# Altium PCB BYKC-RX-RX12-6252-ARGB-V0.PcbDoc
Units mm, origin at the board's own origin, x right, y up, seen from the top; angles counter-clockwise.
Board outline 71.05 x 31.8 mm, 2 copper layers (Top Layer, Bottom Layer); 60 components, 98 nets, 230 pads, 255 vias.
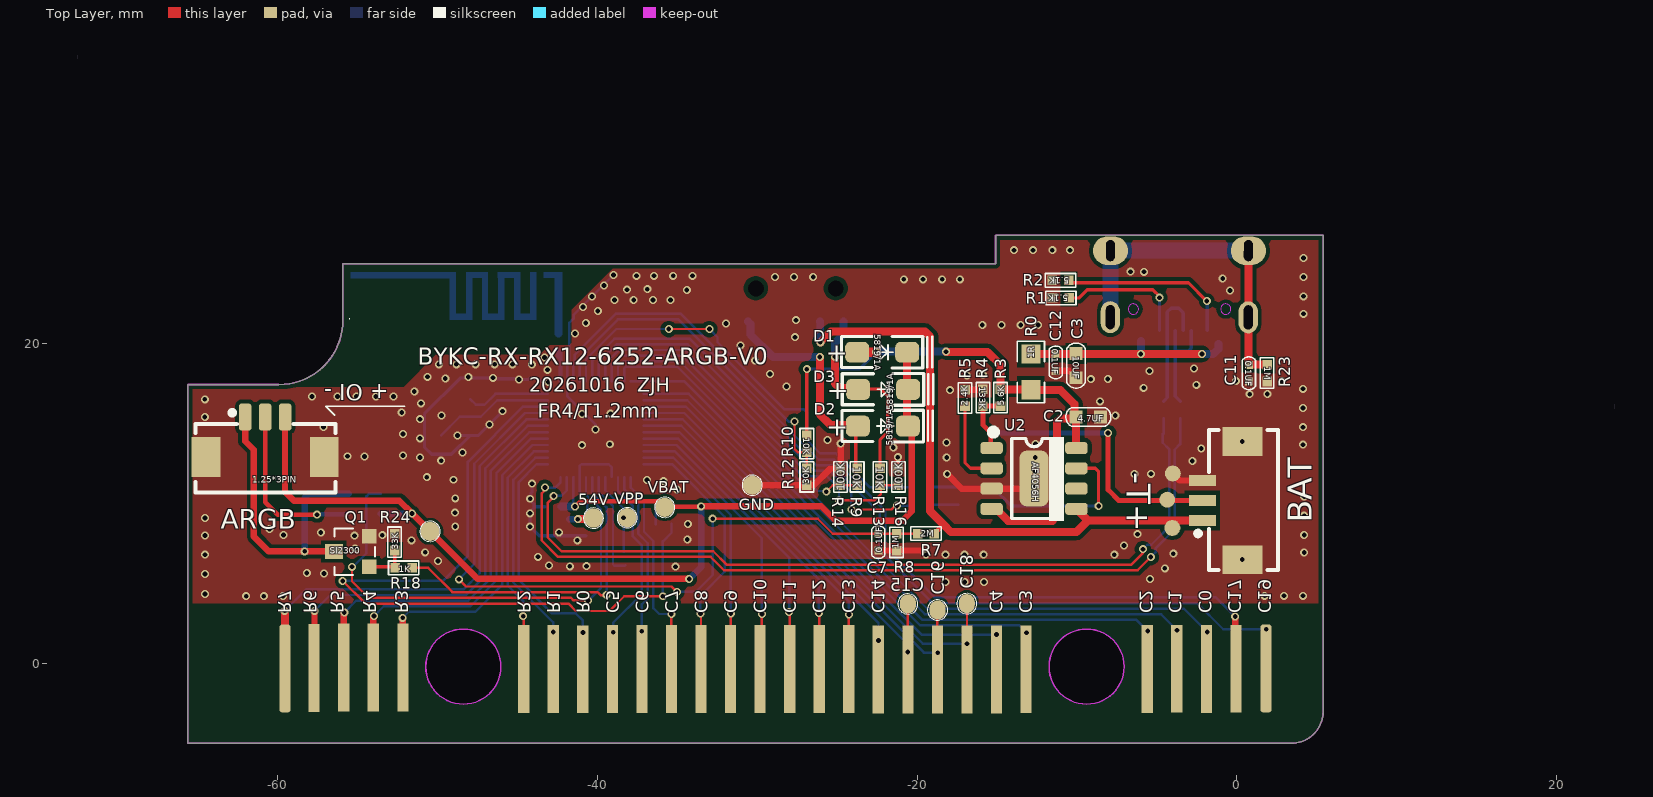
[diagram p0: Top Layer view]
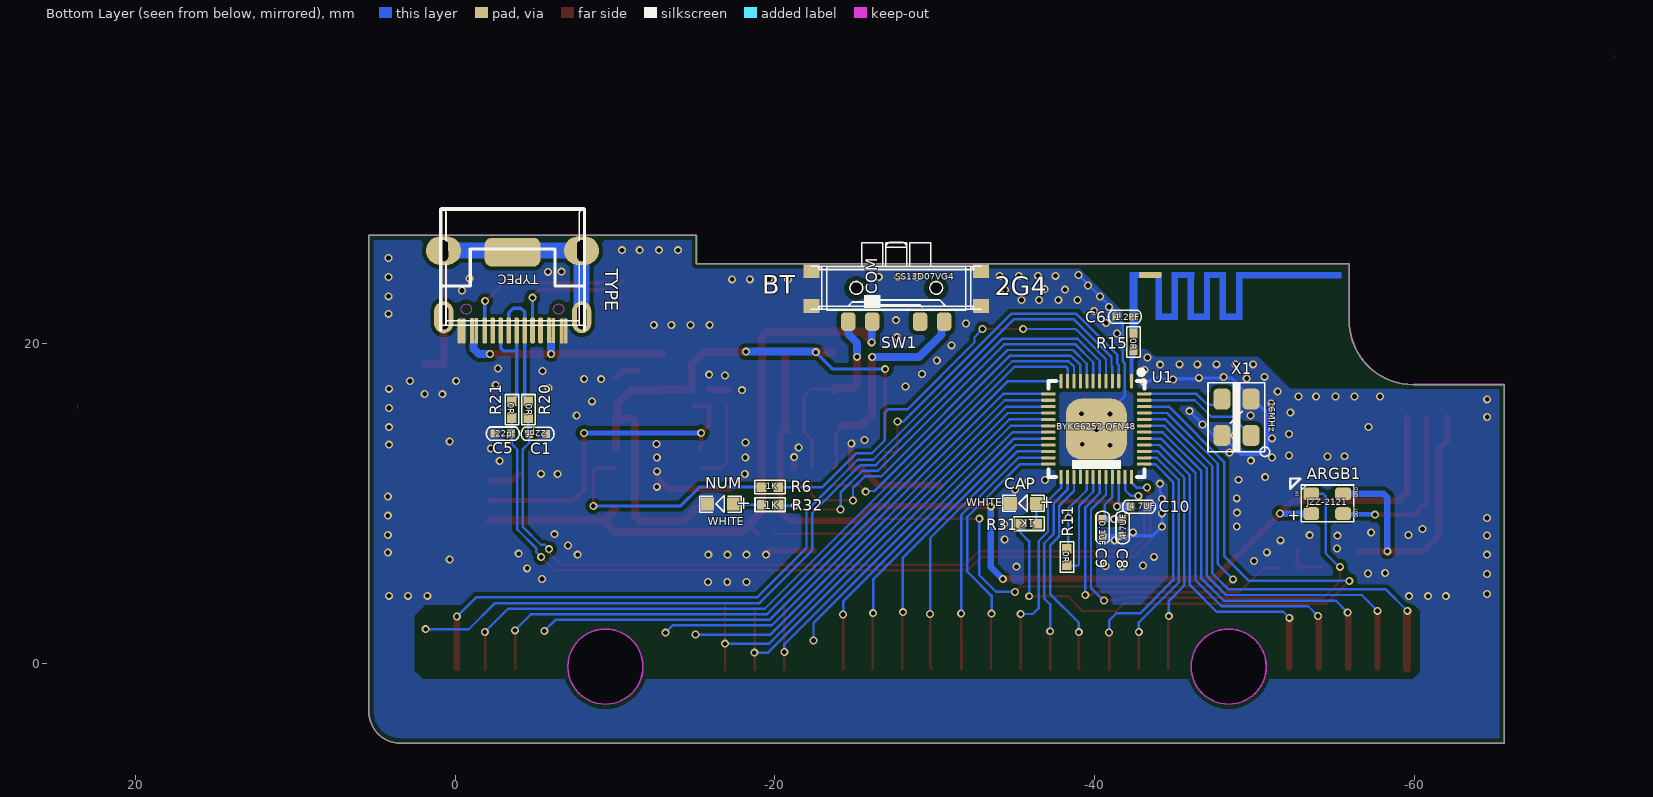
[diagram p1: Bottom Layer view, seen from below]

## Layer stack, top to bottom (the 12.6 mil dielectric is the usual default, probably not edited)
Top Solder: solder mask 0.0102, Solder Resist, Dk 3.5
Top Layer: signal copper 0.0356
Dielectric 1: dielectric 0.32, FR-4, Dk 4.8
Bottom Layer: signal copper 0.0356
Bottom Solder: solder mask 0.0102, Solder Resist, Dk 3.5

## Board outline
-65.644,-5.023 -65.644,17.427 -59.934,17.427 ccw(c-59.934,21.427) -55.934,21.427 -55.934,24.977 -15.094,24.977 -15.094,26.777 5.406,26.777 5.406,-3.023 cw(c3.406,-3.023) 3.406,-5.023
cut-out: -11.744,-0.223 ccw(c-9.394,-0.223) -9.394,-2.573 ccw(c-9.394,-0.223) -7.044,-0.223 ccw(c-9.394,-0.223) -9.394,2.127 ccw(c-9.394,-0.223)
cut-out: -50.744,-0.223 ccw(c-48.394,-0.223) -48.394,-2.573 ccw(c-48.394,-0.223) -46.044,-0.223 ccw(c-48.394,-0.223) -48.394,2.127 ccw(c-48.394,-0.223)

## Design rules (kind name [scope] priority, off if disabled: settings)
Clearance [All] p1: gap=0.199 ignorepadtopadclearanceinfootprint=FALSE except(0.25: Arc-Fill Arc-Poly Arc-Region Track-Fill Track-Poly Track-Region SMDPad-Fill SMDPad-Poly SMDPad-Region THPad-Fill THPad-Poly THPad-Region Via-Fill Via-Poly Via-Region Fill-Fill Fill-Poly Fill-Region Poly-Poly Poly-Region Region-Region)
DiffPairsRouting [All] p1: maxlimit=0.254 minlimit=0.2 mostfreqgap=0.2 toplayer_minwidth=0.2 toplayer_maxwidth=0.2 toplayer_prefwidth=0.2 bottomlayer_minwidth=0.2 bottomlayer_maxwidth=0.2 bottomlayer_prefwidth=0.2 maxuncoupledlength=12.7
PolygonConnect [All] p1: connectstyle=Direct reliefconductorwidth=0.254 reliefentries=4 polygonreliefangle="90 Angle" airgapwidth=0.254
RoutingVias [All] p1: holewidth=0.3 width=0.5 viastyle="Through Hole" minholewidth=0.3 minwidth=0.5 maxholewidth=0.3 maxwidth=0.5
SolderMaskExpansion [All] p1: expansion=0.102 istentingtop=FALSE
Width [All] p1: maxlimit=1 minlimit=0.15 preferedwidth=0.15
29 further rules are at their usual default settings.

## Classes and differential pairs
component class "BYKC_PX781MAX_6625(CD) V1.0": ARGB BAT C1 C2 C3 C5 C6 C8 C9 C10 D1 D2 D3 Q1 R1 R2 R3 R4 R5 R6 R7 R8 R10 R11 R12 R20 R21 SW1 U1 U2 X1

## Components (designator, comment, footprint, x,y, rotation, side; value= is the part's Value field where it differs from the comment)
54V "" TP_1.2C#1 -40.243,9.077 r270 top (schematic designator T3)
ARGB "1.25*3PIN" "3PIN 间距1.25MM"#1 -60.791,14.141 r0 top locked (schematic designator H2)
ARGB1 "JZZ-2121" ARGB-2121-JZZ -54.561,9.991 r90 bottom locked
BAT "" "3PIN 间距1.25MM"#2 -0.901,10.171 r90 top locked (schematic designator BAT1)
C1 "22pf" 0402c -5.152,14.344 r0 bottom value=30pF
C2 "4.7UF" 0603C -10.051,15.401 r0 top
C3 "10UF" 0603C -10.051,17.847 r90 top value=4.7UF
C5 "22pf" 0402c -2.975,14.359 r180 bottom value=30pF
C6 "1.2PF" 0402c -41.9,21.67 r180 bottom value=1.2pF
C7 "0.1UF" 0402c -22.431,7.566 r90 top value=30pF
C8 "4.7UF" 0402c -41.76,8.48 r270 bottom value=10uF
C9 "0.1uF" 0402c -40.51,8.48 r270 bottom
C10 "4.7UF" 0402c -42.781,9.781 r180 bottom value=10uF
C11 "0.1UF" 0402C 0.759,18.131 r270 top
C12 "0.1UF" 0402C -11.331,18.811 r90 top
CAP "WHITE" 0603LED -35.551,9.991 r0 bottom locked (schematic designator LED2)
D1 "5819/1A" 1206D#1 -22.14,19.45 r0 top
D2 "5819/1A" 1206D#2 -22.1,14.83 r0 top
D3 "5819/1A" 1206D#2 -22.08,17.12 r0 top
GND "" TP_1.2C#1 -30.325,11.14 r0 top (schematic designator T3)
NUM "WHITE" 0603LED -16.591,9.951 r0 bottom locked (schematic designator LED3)
Q1 "SI2300" SOT-23 -55.391,6.971 r90 top
R0 "1R" 0805R -12.881,18.221 r90 top value=5.1K (schematic designator R15)
R1 "5.1K" 0402R#1 -10.481,22.851 r180 top
R2 "5.1K" 0402R#1 -11.551,23.951 r0 top
R3 "5.6K" 0402R#1 -14.781,17.131 r270 top
R4 "133K" 0402R#1 -15.881,16.081 r90 top
R5 "2.4K" 0402R#1 -17.001,17.111 r270 top
R6 "1K" 0402R#1 -19.161,11.011 r180 bottom
R7 "2M" 0402R#1 -19.971,8.101 r0 top
R8 "1M" 0402R#1 -21.281,7.031 r90 top
R9 "10K" 0402R#1 -23.751,12.181 r270 top value=1K (schematic designator R10)
R10 "10K" 0402R#1 -26.901,14.251 r270 top
R11 "0R" 0402R#1 -38.27,6.11 r90 bottom
R12 "30K" 0402R#1 -26.901,11.131 r90 top
R13 "10K" 0402R#1 -22.321,12.181 r270 top value=1K (schematic designator R10)
R14 "100K" 0402R#1 -24.801,11.121 r90 top value=1K (schematic designator R10)
R15 "0R" 0402R#2 -42.431,19.571 r90 bottom (schematic designator R5)
R16 "100K" 0402R#1 -21.171,11.131 r90 top value=1K (schematic designator R10)
R18 "1K" 0402R#1 -51.601,5.961 r180 top (schematic designator R13)
R20 "0R" 0402R#1 -4.575,16.381 r270 bottom
R21 "0R" 0402R#1 -3.541,16.381 r270 bottom
R23 "1M" 0402R#3 1.899,18.141 r270 top
R24 "33K" 0402R#1 -52.691,7.041 r90 top value=1K (schematic designator R13)
R31 "1K" 0402R#1 -36.42,8.72 r0 bottom (schematic designator R10)
R32 "1K" 0402R#1 -19.181,9.911 r180 bottom (schematic designator R12)
SW1 "SS13D07VG4" "SW  贴片8PIN" -27.591,22.951 r180 bottom locked
T3 "" TP_1.2C#1 -50.471,8.231 r180 top
T3 "" TP_1.2C#2 -16.896,3.729 r0 top
T3 "" TP_1.2C#2 -18.726,3.329 r0 top
T3 "" TP_1.2C#2 -20.586,3.709 r0 top
TYPE "TYPEC" TYPE16-3D -3.601,23.991 r180 bottom locked
U1 "BYKC6252-QFN48" QFN48-6*6 -40.116,14.645 r180 bottom locked (schematic designator U4)
U2 "AF4056H" SOP8A -12.686,11.548 r0 top locked
VBAT "" TP_1.2C#1 -35.781,9.746 r270 top (schematic designator T3)
VPP "" TP_1.2C#1 -38.151,9.101 r0 top (schematic designator T3)
X1 "16MHz" 3D-3225-4P -48.881,15.381 r90 bottom
? "" ANT0 -46.451,23.381 r90 bottom locked
? "" P1#1 -59.531,-0.308 r180 top
? "" P1#2 -1.582,-0.305 r180 top

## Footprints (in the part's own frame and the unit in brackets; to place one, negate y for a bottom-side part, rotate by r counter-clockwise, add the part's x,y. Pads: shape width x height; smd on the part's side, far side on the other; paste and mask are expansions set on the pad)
3D-3225-4P [mm] "3.2*2.5*0.7mm(长宽高)"
  rrect50% 1.3x1.05 smd: 1(-1.14,-0.91) 2(-1.14,0.91) 3(1.14,0.91) 4(1.14,-0.91)
  silkscreen extent -2.46,-2.08 2.22,1.78, body extent -1.6,-1.25 1.6,1.25, height 0.7
"3PIN 间距1.25MM"#1 [mm]
  rrect50% 0.8x1.7 smd paste+0 mask+0.05: 1(-1.25,1.25) 2(0,1.25) 3(1.25,1.25)
  rect 1.8x2.5 smd paste+0 mask+0.05: 4(-3.7,-1.25) 5(3.7,-1.25)
  silkscreen extent -4.35,-3.47 4.4,1.67
"3PIN 间距1.25MM"#2 [mm]
  rect 0.7x1.7 smd paste+0 mask+0.05: 1(-1.25,1.25) 2(0,1.25) 3(1.25,1.25)
  rect 1.8x2.5 smd paste+0 mask+0.05: 4(-3.7,-1.25) 5(3.7,-1.25)
  silkscreen extent -4.35,-3.47 4.4,1.67
0402c [mm]
  rect 0.5x0.5 smd: 1(-0.525,0) 2(0.525,0)
  silkscreen extent -1.02,-0.42 1.02,0.41
0402C [mm]
  rect 0.5x0.5 smd: 1(-0.525,0) 2(0.525,0)
  silkscreen extent -1.02,-0.42 1.02,0.41, body extent -0.52,-0.28 0.54,0.28, height 0.25
0402R#1 [mm]
  rect 0.6x0.6 smd: 1(0,0) 2(1.05,0)
  silkscreen extent -0.42,-0.42 1.47,0.42
0402R#2 [mm]
  rect 0.6x0.5 smd: 1(0,0) 2(1.05,0)
  silkscreen extent -0.42,-0.43 1.47,0.42
0402R#3 [mm]
  rect 0.6x0.6 smd: 1(-0.525,0) 2(0.525,0)
  silkscreen extent -0.95,-0.42 0.95,0.42, body extent -0.59,-0.19 0.63,0.22, height 0.25
0603C [mm]
  rect 0.8x0.8 smd: 1(0,0) 2(1.524,0)
  silkscreen extent -0.65,-0.58 2.17,0.58
0603LED [mm]
  rect 0.8x0.8 smd: 1(-0.8,0) 2(0.8,0)
  silkscreen extent -1.3,-0.53 1.3,0.51, body extent -0.85,-0.45 0.85,0.45, height 0.9
0805R [mm]
  rect 1.2x1.2 smd: 1(-1.125,0) 2(1.125,0)
  silkscreen extent -1.92,-0.85 1.92,0.85
1206D#1 [mm]
  rrect50% 1.5x1.3 smd: 2(1.52,0) D(-1.61,0)
  silkscreen extent -2.6,-0.99 3.08,0.99, body extent -1.84,-0.8 1.86,0.8, height 1.2
1206D#2 [mm]
  rrect50% 1.5x1.3 smd: 1(-1.61,0) 2(1.52,0)
  silkscreen extent -2.6,-0.99 3.08,0.99, body extent -1.84,-0.8 1.86,0.8, height 1.2
ANT0 [mm]
  rrect50% 0.4x1.4 smd: 1(0.9,2.96)
  Top Layer region: -1.501,2.34 -1.501,1.489 -1.901,1.489 -1.901,2.34
  Top Layer region: 0.696,-2.4 1.095,-2.4 1.095,-9.017 0.696,-9.017
  Top Layer region: 1.097,1.633 1.097,1.233 -1.903,1.233 -1.903,1.633
  Top Layer region: 1.098,1.34 1.098,0.211 0.698,0.211 0.698,1.34
  Top Layer region: 0.85,0.633 0.85,0.211 -1.902,0.211 -1.902,0.633
  Top Layer region: -1.503,0.36 -1.503,-0.59 -1.903,-0.59 -1.903,0.36
  Top Layer region: 1.099,-0.389 1.099,-0.789 -1.903,-0.789 -1.903,-0.389
  Top Layer region: 1.098,-0.68 1.098,-1.783 0.701,-1.783 0.701,-0.68
  Top Layer region: 0.9,-1.384 0.9,-1.784 -1.904,-1.784 -1.904,-1.384
  Top Layer region: -1.505,-1.56 -1.505,-2.65 -1.905,-2.65 -1.905,-1.56
  Top Layer region: 1.096,-2.401 1.096,-2.801 -1.904,-2.801 -1.904,-2.401
  Top Layer region: 1.1,2.641 1.1,2.241 -1.902,2.241 -1.902,2.641
ARGB-2121-JZZ [mm] "JZZ晶之"
  rrect50% 0.8x1 smd: 1(-0.64,-1) 2(0.6,-1) 3(-0.64,1) 4(0.6,1)
  silkscreen extent -1.15,-1.65 1.56,2.32, body extent -1.4,-1.76 1.4,1.74, height 0.21
P1#1 [mm] "金手指"
  rect 0.7x5.5 smd: 1(-1.791,0.002)
P1#2 [mm] "金手指"
  rect 0.7x5.5 smd: 1(-1.531,0.054)
QFN48-6*6 [mm]
  rrect50% 0.19x0.9 smd paste-100 mask+0.051: 1(2.2,3) 3(1.4,3) 4(1,3) 5(0.6,3) 6(0.2,3) 7(-0.2,3) 8(-0.6,3) 9(-1,3) 10(-1.4,3) 11(-1.8,3) 12(-2.2,3) 25(-2.2,-3) 26(-1.8,-3) 27(-1.4,-3) 28(-1,-3) 29(-0.6,-3) 30(-0.2,-3) 31(0.2,-3) 32(0.6,-3) 33(1,-3) 34(1.4,-3) 35(1.8,-3) 36(2.2,-3)
  rrect50% 0.45x1.5 on Bottom Overlay paste-100 mask+0.051: 2(1.8,3)
  rrect50% 0.9x0.19 smd paste-100 mask+0.051: 13(-3,2.2) 14(-3,1.8) 15(-3,1.4) 16(-3,1) 17(-3,0.6) 18(-3,0.2) 19(-3,-0.2) 20(-3,-0.6) 21(-3,-1) 22(-3,-1.4) 23(-3,-1.8) 24(-3,-2.2) 37(3,-2.2) 38(3,-1.8) 39(3,-1.4) 40(3,-1) 41(3,-0.6) 42(3,-0.2) 43(3,0.2) 44(3,0.6) 45(3,1) 46(3,1.4) 47(3,1.8) 48(3,2.2)
  rrect50% 3.8x3.8 smd paste-100 mask+0.051: 49(0.001,-0.001)
  silkscreen extent -3,-3 3,3.7
SOP8A [mm] "5*6*1.8mm（长宽高）"
  rrect50% 1.4x0.75 smd: 1(-2.65,1.905) 2(-2.65,0.635) 3(-2.65,-0.635) 4(-2.65,-1.905) 5(2.65,-1.905) 6(2.65,-0.635) 7(2.65,0.635) 8(2.65,1.905)
  rrect50% 1.8x3.5 smd: 9(0,0)
  silkscreen extent -2.69,-2.66 1.89,3.05, body extent -3,-2.5 3,2.5, height 1.9
SOT-23 [mil]
  rect 36x36 smd: 1(-37.5,-43.48) 2(37.5,-43.48)
  rect 36x43.94 smd: 3(0.5,43.48)
  silkscreen extent -58,-57 57,42
"SW  贴片8PIN" [mm]
  rrect50% 0.9x1.15 smd: 1(-3,-1.588) 2(-1.5,-1.588) 3(1.5,-1.588) 4(3,-1.588)
  rect 1x0.9 smd: 5(-5.3,-0.613) 6(-5.3,1.587) 7(5.3,1.587) 8(5.3,-0.613)
  round 0 hole 1: ""(-2.5,0.5) ""(2.5,0.5)
  silkscreen extent -4.35,-0.86 4.35,3.34
TP_1.2C#1 [mm]
  round 1.2 smd: 1(0.006,-0.009)
  silkscreen extent -0.63,-0.64 0.64,0.63
TP_1.2C#2 [mm]
  oval 1x1.2 smd: 1(0.006,-0.009)
  silkscreen extent -0.63,-0.64 0.64,0.63
TYPE16-3D [mm]
  oval 2.2x1.8 hole 0.55 slot 1.3 at 90.55 deg: 0(-4.33,1.81) 0(4.3,1.81)
  oval 1.2x2 hole 0.55 slot 1.5 at 90.55 deg: 0(-4.32,-2.36) 0(4.31,-2.35)
  rrect50% 3.5x1.8 smd: 0(-0.01,1.72)
  rrect50% 0.23x1.55 smd: 1(-3.34,-3.22) 2(-3.08,-3.22) 15(3.06,-3.22) 16(3.32,-3.22)
  rrect50% 0.23x1.6 smd: 3(-2.55,-3.2) 4(-2.29,-3.2) 13(2.27,-3.18)
  rrect50% 0.3x1.6 smd: 5(-1.758,-3.183) 6(-1.258,-3.183) 7(-0.758,-3.183) 8(-0.258,-3.183) 9(0.242,-3.183) 10(0.742,-3.183) 11(1.242,-3.183) 12(1.742,-3.183)
  rrect50% 0.23x1.58 smd: 14(2.53,-3.19)
  Keep-Out Layer circle w0.05: c-2.913,-1.843 r0.325
  Keep-Out Layer circle w0.05: c2.867,-1.843 r0.325
  silkscreen extent -4.51,-3.14 4.49,4.41, body extent -4.49,-3.57 4.45,4.33, height 3.25

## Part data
54V GND T3 T3 T3 T3 VBAT VPP: library part TEST_POINT
ARGB: library part PZ254V-11-03P, Color=黑色, Current Rating (Max)=3A, JLCPCB Part Class="Extended Part", LCSC Part Name="间距:2.54mm 1x3P 直插 方针", Manufacturer=XFCN(兴飞), Operating Temperature Range=-40℃~+105℃, Voltage Rating (Max)=250V
BAT: library part Battery, "Multicell Battery"
C1 C5 C6 C7 C8 C9 C10: library part CAP_0603
C2 C3: library part Cap, "Capacitor"
CAP NUM: library part LED_0603-R
D1: library part "D Schottky", "Schottky Diode"
D2 D3: library part D_1N4007A
Q1: library part SI2301-ZE, Continuous Drain Current (Id)=2.3A, Drain Source On Resistance (RDS(on)@Vgs,Id)=126mΩ@4.5V, Drain Source Voltage (Vdss)=20V, Gate Threshold Voltage (Vgs(th)@Id)=1V@250uA, Input Capacitance (Ciss@Vds)=285pF, JLCPCB Part Class="Extended Part", LCSC Part Name="1个P沟道 耐压:20V 电流:2.3A", Manufacturer="HXY MOSFET(华轩阳电子)", Manufacturer Part=SI2300-ZE, Power Dissipation (Pd)=700mW
R0 R1 R2 R7 R8 R9 R10 R11 R12 R13 R14 R16 R18 R20 R21 R24 R31 R32: library part Res_0603
R3 R4 R5 R6 R15: library part Res2, "Resistor"
SW1: Actuator Color=-, Current Rating (DC)=500mA, JLCPCB Part Class="Extended Part", LCSC Part Name="4脚3三档位SS13D07VG2 1P3T立式拨动开关,柄长4MM", Manufacturer="SHOU HAN(首韩)", Operating Temperature=-10℃~+50℃, Voltage Rating (DC)=50V
U1: library part "BYC6625 QFN48"
U2: library part "4057 SOP-8"
X1: library part XL7EL89COI-111YLC-16M, Equivalent Series Resistance (ESR)=-, External load capacitor=12pF, Frequency Stability(Full temperature range)=±20ppm, JLCPCB Part Class="Extended Part", LCSC Part Name="16MHz ±10ppm 12pF", Manufacturer=YXC(扬兴晶振), Normal temperature Frequency Tolerance=±10ppm, Operating Temperature=-40℃~+85℃

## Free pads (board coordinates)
  rect 0.7x5.5 smd: 1(-1.891,-0.379) 4(-3.751,-0.359) 5(-5.597,-0.378) 6(-13.181,-0.389) 7(-15.03,-0.403) 8(-16.879,-0.409) 9(-18.728,-0.409) 10(-20.577,-0.396) 11(-22.426,-0.396) 12(-24.275,-0.384) 13(-26.124,-0.377) 14(-27.974,-0.371) 15(-29.823,-0.371) 16(-31.672,-0.371) 17(-33.521,-0.365) 18(-35.37,-0.36) 19(-37.219,-0.384) 20(-39.068,-0.377) 21(-40.917,-0.39) 22(-42.766,-0.36) 23(-44.615,-0.372) 25(-54.031,-0.279) 26(-55.881,-0.279) ""(-52.171,-0.275)
  round 1 smd: 27(-4.001,11.861) 28(-4.351,10.221) 29(-4.031,8.451)
  rrect50% 0.7x5.5 smd: 30(-59.56,-0.34) 30(1.83,-0.34)

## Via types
v1: diameter 0.5, hole 0.3, Top Layer to Bottom Layer, 255 vias

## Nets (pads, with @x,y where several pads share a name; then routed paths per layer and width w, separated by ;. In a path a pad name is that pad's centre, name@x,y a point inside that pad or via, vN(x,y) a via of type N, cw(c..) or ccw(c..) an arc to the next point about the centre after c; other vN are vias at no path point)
001: ARGB1.1 ARGB.2 | length 10.9
  Top Layer w0.3: ARGB.2 -60.791,10.061 -60.011,9.281 v1(-57.551,9.281)
  Bottom Layer w0.3: v1(-57.551,9.281) -57.516,9.316 -55.596,9.316 ARGB1.1
002: 
2G4: R9.2 R14.1 U1.9 | length 20.4
  Top Layer w0.15: v1(-25.681,10.721) -25.281,11.121 R14.1 ; R14.1@-24.791,11.131 R9.2 R9.2@-23.681,11.131
  Bottom Layer w0.15: U1.9 -39.116,18.639 -38.517,19.238 -34.709,19.238 -26.24,10.768 -25.729,10.768 v1(-25.681,10.721)
003: 
004: 
005: 
5V: C2.1 D1.D R0.1 R3.1 R10.1 U2.4 U2.8 | length 38.9
  Top Layer w0.2: R10.1@-26.901,14.451 -26.901,18.389 v1(-26.9,18.39)
  Top Layer w0.5: v1(-18.19,19.48) -18.181,19.471 -15.591,19.471 -14.781,18.661 R3.1 ; U2.4 -15.011,9.643 -14.886,9.518 -14.886,9.476 -14.31,8.9 -11.544,8.9 -11.251,9.193 -11.251,15.111 -11.071,15.291 C2.1@-10.051,15.291 ; R3.1@-14.701,17.131 -12.981,17.131 -12.941,17.091 -11.041,17.091 -10.147,16.197 -10.147,15.386 C2.1@-10.051,15.291 ; U2.8 -10.051,13.469 C2.1@-10.051,15.291
  Top Layer w0.6: D1.D@-23.6,19.45 v1(-22.56,19.45)
  Bottom Layer w0.2: v1(-26.9,18.39) -23.62,18.39 v1(-22.56,19.45)
  Bottom Layer w0.5: v1(-22.56,19.45) -22.53,19.48 v1(-18.19,19.48)
5VLVD: C7.2 R7.1 R8.2 U1.45 | length 46.9
  Top Layer w0.15: v1(-48.67,5.24) -48.219,4.789 -35.369,4.789 v1(-35.03,4.45) ; v1(-32.79,9.03) -26.22,9.03 -25.281,8.091 C7.2 -19.981,8.091 R7.1
  Bottom Layer w0.15: v1(-48.67,5.24) -47.713,6.197 -47.713,12.475 -44.544,15.645 U1.45 ; v1(-35.03,4.45) -33.85,4.45 -32.79,5.51 v1(-32.79,9.03)
006: 
007: 
008: 
009: 
54E_CTRL: R18.1 U1.31 | length 20.6
  Top Layer w0.15: R18.1 -50.601,5.961 -49.08,4.44 -39.993,4.44 -39.804,4.251 v1(-39.421,4.251)
  Bottom Layer w0.15: U1.31 -40.316,10.629 -39.43,9.743 v1@-39.43,4.251
BAT+: BAT.1 pad.29 R7.2 SW1.2 U2.5 | length 39.2
  Top Layer w0.3: R7.2 -18.356,8.666
  Top Layer w0.5: v1(-26.06,20.07) -25.38,20.75 -19.5,20.75 -19.19,20.44 -19.19,9.5 -19.17,9.48 -18.356,8.666 -17.891,8.201 -10.034,8.201 -9.314,8.921 ; U2.5 -9.314,8.921 ; BAT.1 -9.314,8.921
  Bottom Layer w0.5: SW1.2 -26.061,21.333 -26.061,20.071 v1(-26.06,20.07)
BT: R13.2 R16.1 U1.8 | length 24.9
  Top Layer w0.15: v1(-24.89,10.18) -22.652,10.18 -22.261,10.571 -22.261,10.971 -22.261,11.071 R13.2 -22.261,11.131 R16.1
  Bottom Layer w0.15: U1.8 -39.516,18.733 -38.662,19.587 -34.565,19.587 -26.657,11.679 -25.619,11.679 -24.89,10.95 v1(-24.89,10.18)
C0: pad.1 U1.10 | length 47.3
  Top Layer w0.15: pad.1 -1.89,-0.378 pad.1@-1.89,1.95
  Bottom Layer w0.15: U1.10 -38.716,18.546 -38.373,18.889 -34.854,18.889 -19.366,3.401 -3.301,3.401 v1(-1.85,1.95)
C1: pad.4 U1.11 | length 44.7
  Top Layer w0.15: pad.4 pad.4@-3.751,2.05
  Bottom Layer w0.15: U1.11 -38.316,18.452 -38.228,18.54 -34.998,18.54 -19.51,3.052 -4.732,3.052 v1(-3.73,2.05)
C1A: 
C2: pad.5 U1.12 | length 38.8
  Bottom Layer w0.15: U1.12 -34.597,17.645 -19.655,2.703 -6.273,2.703 v1(-5.57,2)
C2A: 
C3: pad.6 U1.13 | length 30.2
  Bottom Layer w0.15: U1.13 -34.29,16.845 -19.8,2.354 -13.604,2.354 v1(-13.15,1.9)
C4: pad.7 U1.14 | length 28.2
  Bottom Layer w0.15: U1.14 -34.384,16.445 -19.719,1.78 v1(-15.04,1.78)
C5: pad.20 U1.27 | length 13.4
  Top Layer w0.15: pad.20 -39,-0.31 pad.20@-39,1.93
  Bottom Layer w0.15: v1(-39.02,1.93) -39.02,2.52 -37.221,4.319 -37.221,7.361 -37.801,7.941 -37.801,9.851 -38.716,10.766 U1.27
C6: pad.19 U1.26 | length 12.8
  Top Layer w0.15: pad.19 pad.19@-37.219,1.99
  Bottom Layer w0.15: U1.26 -38.316,10.859 -37.441,9.985 -37.441,8.075 -36.859,7.493 -36.859,4.041 -37.23,3.67 v1(-37.23,1.99)
C7: pad.18 U1.25 | length 13.5
  Top Layer w0.15: v1(-35.38,3.07) -35.38,-0.349 pad.18
  Bottom Layer w0.15: U1.25 -37.916,10.976 -37.092,10.152 -37.092,8.22 -36.51,7.637 -36.51,3.44 -36.14,3.07 v1(-35.38,3.07)
C8: pad.17 U1.24 | length 16.6
  Top Layer w0.15: v1(-33.56,3.09) -33.521,3.051 pad.17
  Bottom Layer w0.15: U1.24 -35.335,12.445 -32.04,9.15 -32.04,5.72 -33.56,4.2 v1(-33.56,3.09)
C9: pad.16 U1.23 | length 18.6
  Top Layer w0.15: pad.16 -31.66,-0.36 v1(-31.66,3.11)
  Top Layer w0.18: pad.16 pad.16@-31.672,1.631
  Bottom Layer w0.15: U1.23 -35.242,12.845 -31.66,9.263 v1(-31.66,3.11)
C10: pad.15 U1.22 | length 17.9
  Top Layer w0.15: pad.15 -29.71,-0.259 v1(-29.71,3.07)
  Bottom Layer w0.15: U1.22 -35.148,13.245 -29.71,7.807 v1(-29.71,3.07)
C11: pad.14 U1.21 | length 19
  Top Layer w0.15: v1(-28.01,3.18) -27.974,3.144 pad.14
  Bottom Layer w0.15: U1.21 -35.055,13.645 -28.01,6.6 v1(-28.01,3.18)
C12: pad.13 U1.20 | length 20.2
  Top Layer w0.15: v1(-26.15,3.12) -26.124,3.094 pad.13
  Bottom Layer w0.15: U1.20 -34.961,14.045 -26.15,5.234 v1(-26.15,3.12)
C13: pad.12 U1.19 | length 21.5
  Top Layer w0.15: pad.12 -24.27,-0.378 v1(-24.27,3.04)
  Bottom Layer w0.15: U1.19 -34.868,14.445 -24.27,3.847 v1(-24.27,3.04)
C14: pad.11 U1.18 | length 20.9
  Bottom Layer w0.15: U1.18 -34.758,14.845 -22.415,2.502 -22.415,1.415 v1(-22.42,1.41)
C15: pad.10 T3.1@-20.58,3.7 U1.17 | length 26.9
  Top Layer w0.15: T3.1@-20.58,3.7 -20.577,3.697 pad.10
  Bottom Layer w0.15: U1.17 -34.665,15.245 -20.595,1.175 -20.595,0.705 v1(-20.59,0.7)
C16: pad.9 T3.1@-18.72,3.32 U1.16 | length 28.3
  Top Layer w0.15: pad.9 -18.728,3.312 T3.1@-18.72,3.32
  Bottom Layer w0.15: U1.16 -34.571,15.645 -19.576,0.65 v1(-18.71,0.65)
C17: ?.1@-0.051,-0.359 U1.4 | length 55.8
  Top Layer w0.15: ?.1@-0.1,-0.31 ?.1@-0.051,-0.359
  Top Layer w0.4: ?.1@-0.1,-0.31 v1(-0.1,2.91)
  Bottom Layer w0.15: U1.4 -41.116,18.55 -41.065,18.601 -41.065,19.158 -38.723,21.5 -34.934,21.5 -26.16,12.726 -25.185,12.726 -21.981,9.522 -21.981,7.191 -18.92,4.13 -1.32,4.13 v1(-0.1,2.91)
C18: pad.8 T3.1@-16.89,3.72 U1.15 | length 30.5
  Top Layer w0.15: T3.1@-16.89,3.72 -16.879,3.709 pad.8
  Bottom Layer w0.15: U1.15 -34.478,16.045 -19.647,1.214 -16.884,1.214 v1(-16.88,1.21)
C18A: 
C19: pad.30@1.83,-0.34 U1.6 | length 52.9
  Bottom Layer w0.15: U1.6 -40.316,18.92 -38.951,20.285 -34.212,20.285 -26.304,12.377 -25.33,12.377 -22.33,9.377 -22.33,7.046 -19.034,3.75 -2.48,3.75 -0.845,2.115 1.845,2.115 v1(1.85,2.12)
CAP: R31.2 U1.46 | length 46.7
  Top Layer w0.15: v1(-55.94,5.14) -54.52,3.72 -41.82,3.72 -41.36,3.26 -39.25,3.26 -38.33,4.18 v1(-35.91,4.18)
  Bottom Layer w0.15: v1(-55.94,5.14) -49.67,5.14 -48.11,6.7 -48.11,12.59 -44.655,16.045 U1.46 ; v1(-35.91,4.18) -35.91,7.61 -35.37,8.15 R31.2
CD: R6.2 U1.5 | length 28
  Top Layer w0.15: v1(-35.54,20.9) v1(-33,20.9)
  Bottom Layer w0.15: U1.5 -40.716,19.013 -38.83,20.9 v1(-35.54,20.9) ; v1(-33,20.9) -32.49,20.39 -32.49,20.07 -28.29,15.87 -27.08,15.87 -26.88,15.67 -26.88,13.94 -26.06,13.12 -25.086,13.12 -22.977,11.011 R6.2
CHECK_5V: R10.2 R12.2 U1.3 | length 22.9
  Top Layer w0.15: v1@-27.671,15.11 -27.671,13.391 -27.481,13.201 R10.2 R12.2
  Bottom Layer w0.15: U1.3 -41.516,18.644 -41.414,18.746 -41.414,19.303 -38.868,21.849 -34.779,21.849 -28.04,15.11 v1(-27.68,15.11)
D+: R21.1 TYPE.7 TYPE.9 | length 6.7
  Bottom Layer w0.2: TYPE.9 -3.843,19.531 ; R21.1 -3.843,16.683 -3.843,19.531 ; TYPE.7 -2.843,19.709 -3.021,19.531 -3.843,19.531
D-: R20.1 TYPE.8 TYPE.10 | length 8
  Bottom Layer w0.2: R20.1 -4.343,16.613 TYPE.10 -4.343,21.969 -4.111,22.201 -3.631,22.201 -3.343,21.913 TYPE.8
DM: C1.2 R20.2 U1.35 | length 52.2
  Top Layer w0.15: v1(-42.741,10.455) -42.741,10.386 -43.121,10.006 -43.121,7.871 -42.241,6.991 -32.761,6.991 -31.93,6.16 -6.592,6.16 -5.875,6.877 v1(-5.875,7.125)
  Bottom Layer w0.15: v1(-42.741,10.455) -42.716,10.481 -42.251,10.481 -41.916,10.816 U1.35 ; v1(-5.875,7.125) -5.6,7.4 -5.353,7.4 -4.23,8.522 -4.23,13.39 -4.627,13.787 C1.2 ; C1.2@-4.575,14.344 R20.2
DP: C5.2 R21.2 U1.36 | length 53.5
  Top Layer w0.15: v1(-43.29,10.98) -43.357,10.913 -43.357,10.752 -43.491,10.618 -43.491,7.671 -42.462,6.642 -32.912,6.642 -32.081,5.811 -6.2,5.811 v1(-5.381,6.63)
  Bottom Layer w0.15: v1(-43.29,10.98) -42.627,10.979 -42.316,11.29 U1.36 ; v1(-5.381,6.63) -5.076,6.935 -5.076,7.176 -3.881,8.371 -3.881,13.361 -3.541,13.701 R21.2
GND: ARGB.4 ARGB.5 BAT.3 BAT.4 BAT.5 C1.1 C2.2 C3.1 C5.1 C6.1 C7.1 C8.2 C9.2 C10.2 C11.2 C12.1 CAP.2 GND.1 NUM.2 pad.27 Q1.2 R1.2 R2.1 R4.2 R5.1 R8.1 R12.1 R14.2 R16.2 R23.2 R24.2 SW1.5 SW1.6 SW1.7 SW1.8 TYPE.1 TYPE.2 TYPE.15 TYPE.16 U1.49 U2.3 U2.9 X1.2 X1.4 | length 59.2
  Top Layer w0.4: GND.1@-30.38,11.07 GND.1 R12.1 -26.461,11.131 -25.421,12.171 -24.761,12.171 -24.786,12.195 -24.786,13.724 v1(-24.78,13.73) ; C7.1 -19.729,7.041 -19.471,6.783 v1(-19.443,6.783) ; v1(-21.211,12.881) -21.211,12.221 R16.2 ; v1(-18.12,11.83) -17.203,10.913 -13.321,10.913 U2.9 ; R5.1@-17.151,17.111 -15.901,17.111 R4.2 ; C12.1@-11.361,18.286 -10.49,18.286 C3.1 ; pad.27 -3.561,11.421 BAT.3
  Bottom Layer w0.15: U1.49@-40.117,14.917 -40.876,15.676 -41.885,16.685 -41.885,18.768 -41.763,18.89 -41.763,21.282 -41.494,21.551 -41.494,21.789 -40.951,22.331 v1(-40.341,22.941) -39.621,23.661 v1(-39.001,24.281)
  Bottom Layer w0.2: v1(-48.761,14.241) X1.2 ; v1(-45.941,15.761) -47.461,14.241 X1.2 ; v1(-44.101,11.221) -44.104,11.218 -44.104,10.671 -44.154,10.621 -44.154,10.338 v1(-44.211,10.281) -44.211,10.2 -43.981,9.97 -43.981,9.711 ; C10.2@-43.276,9.781 -43.911,9.781 -43.981,9.711 ; v1(-43.08,17.59) -43.137,17.647 -43.546,17.647 -43.73,17.831 -44.239,17.831 -44.33,17.74 v1(-44.92,17.74) -44.975,17.795 -46.496,17.795 -46.531,17.831 -48.081,17.831 -48.591,17.831 -50.831,15.591 -50.831,13.521 -50.371,13.061 -49.151,13.061 X1.2 ; C9.2@-40.711,7.966 -43.656,7.966 v1(-44.221,8.531) -44.221,9.452 -43.981,9.692 -43.981,9.711 ; U1.49 U1.49@-40.117,14.917
  other v1: -61.981,4.181 -60.881,4.181 -59.681,4.181 1.749,4.211 2.949,4.211 4.149,4.211 -64.561,4.321 -18.22,5.08 -17.02,5.08 -15.82,5.08 -5.421,5.261 -64.561,5.581 -57.11,5.6 -58.19,5.63 -4.501,5.931 -35.12,6.03 -41.731,6.051 -40.681,6.061 -43.031,6.101 -49.98,6.38 0.348,6.471 -43.721,6.651 -64.561,6.781 -18.231,6.783 -17.031,6.783 -15.831,6.783 -7.661,6.783 -3.971,6.841 -50.78,6.93 4.219,6.921 -55.171,7.171 -7.051,7.351 -51.631,7.681 -41.261,7.681 -34.38,7.74 -55.201,7.971 -64.561,7.981 -53.461,8.001 -59.65,8.02 4.219,8.021 -6.211,8.061 -57.311,8.171 -42.411,8.181 -60.53,8.39 -48.9,8.54 -34.35,8.71 -64.561,9.081 4.219,9.221 -44.221,9.371 -48.91,9.41 -48.9,10.31 4.219,10.421 -35.021,10.851 -12.61,11.03 -35.871,11.381 -36.901,11.451 -49.01,11.47 -50.68,11.63 -6.411,11.831 -5.361,11.841 -12.62,12 -2.781,12.641 -49.781,12.661 -51.101,12.861 -18.15,12.87 -12.61,12.87 -54.58,12.92 -55.65,12.94 -52.16,12.98 -48.451,13.181 -2.221,13.421 -21.491,13.481 -40.971,13.631 4.149,13.661 -39.231,13.691 -12.6,13.7 -18.16,13.8 0.348,13.871 -25.61,13.95 -51.101,14.061 -52.17,14.33 -40.121,14.611 -57.141,14.771 4.149,14.761 -46.761,14.931 -51.101,15.261 -64.571,15.401 -49.761,15.491 -7.601,15.491 -40.971,15.581 -39.191,15.601 -52.25,15.68 4.149,15.961 -51.051,16.251 -8.551,16.381 -64.571,16.501 -57.861,16.671 -56.271,16.671 -55.071,16.671 -53.871,16.671 -52.771,16.671 0.809,16.821 1.909,16.841 -51.461,16.991 -17.941,17.071 4.149,17.161 -5.821,17.221 -28.18,17.31 -2.531,17.411 -0.061,17.651 2.839,17.641 -9.131,17.761 -8.071,17.771 -49.521,17.811 -46.531,17.851 -48.081,17.901 -50.641,17.911 -16.88,18 -15.891,18.041 -29.2,18.09 -5.461,18.271 -43.121,18.351 -2.681,18.431 -49.931,18.691 -48.831,18.691 -47.631,18.691 -46.431,18.691 -45.321,18.691 -44.111,18.671 -30.13,18.93 -43.31,19.12 -31.05,19.88 -27.641,20.391 -41.41,20.62 -15.921,21.151 -14.721,21.151 -13.521,21.151 -12.421,21.151 -31.96,21.25 -40.73,21.27 -27.571,21.451 4.179,21.851 -39.98,22.02 -40.901,22.281 -38.931,22.711 -37.731,22.711 -36.531,22.711 -35.431,22.711 4.179,22.951 -0.431,23.311 -38.15,23.36 -34.41,23.35 -36.88,23.39 -39.591,23.631 -20.831,24.011 -19.631,24.011 -18.431,24.011 -17.331,24.011 -0.881,24.061 4.179,24.151 -28.901,24.161 -27.701,24.161 -26.501,24.161 -37.561,24.231 -36.461,24.231 -35.261,24.231 -34.061,24.231 -5.811,24.481 -6.651,24.491 4.179,25.351 -13.941,25.831 -12.741,25.831 -11.541,25.831 -10.441,25.831
LED_0: 
LED_1: 
LED_2: 
LED_3: 
LED_4: 
LED_5: 
LED_VDD: 
MODE_IO: 
NetANT1_1: ?.1@-43.491,24.281 C6.2 R15.1 R15.2 U1.1 | length 6
  Bottom Layer w0.25: R15.1 -42.316,19.456 U1.1
  Bottom Layer w0.3: -42.431,19.166 R15.1
  Bottom Layer w0.5: R15.2 -42.431,24.201
NetC7_2: 
NetC8_1: 
NetCON1_26: 
NetCON1_27: 
NetCON1_28: 
NetD2_1: D2.1 R9.1 SW1.4 | length 14.5
  Top Layer w0.2: D2.1@-24.311,14.881 -23.84,14.41 -23.84,12.34 R9.1@-23.681,12.181
  Top Layer w0.5: v1(-26.09,19.15) -26.09,15.56 -25.419,14.888 -24.219,14.888 D2.1@-24.211,14.881
  Bottom Layer w0.5: SW1.4 -30.436,21.208 -30.436,20.566 -29.02,19.15 v1(-26.09,19.15)
NetD3_1: D3.1 R13.1 SW1.1 | length 12.5
  Top Layer w0.2: D3.1@-23.69,17.151 -22.287,17.151 -21.84,16.704 -21.84,14.441 -22.321,13.96 R13.1
  Top Layer w0.5: v1(-25.14,19.16) -25.14,17.496 -24.847,17.203 -23.803,17.203 D3.1@-23.69,17.09
  Bottom Layer w0.5: v1(-25.14,19.16) -25.14,20.04 -24.591,20.589 SW1.1
NetH2_1: ARGB1.2 ARGB.1 Q1.3 | length 19.3
  Top Layer w0.4: ARGB.1 -62.041,13.881 -61.5,13.34 -61.5,7.92 -60.564,6.984 Q1.3
  Bottom Layer w0.4: v1(-58.321,6.991) -58.321,10.357 -58.087,10.591 ARGB1.2
NetLED1_2: 
NetLED2_2: CAP.1 R31.1 | length 1.3
  Bottom Layer w0.15: R31.1@-36.361,8.69 -36.351,8.7 CAP.1
NetLED3_2: NUM.1 R32.1 | length 1.7
  Bottom Layer w0.15: R32.1 NUM.1@-17.431,9.911
NetQ1_1: Q1.1 R18.2 R24.1 | length 2.7
  Top Layer w0.2: Q1.1@-54.181,6.021 R18.2@-52.711,6.021 ; R24.1@-52.691,7.111 -52.691,6.041 R18.2@-52.711,6.021 ; R18.2 R18.2@-52.711,6.021
NetQ2_1: 
NetR1_1: R1.1 TYPE.11 | length 8.2
  Top Layer w0.2: R1.1 -9.861,22.851 -9.351,23.361 -5.251,23.361 -4.831,22.942 v1(-4.831,22.861)
  Bottom Layer w0.2: TYPE.11 -4.837,20.814 -4.837,22.855 v1(-4.831,22.861)
NetR2_2: R2.2 TYPE.5 | length 11
  Top Layer w0.2: R2.2 -10.351,23.801 -3.021,23.801 v1(-1.871,22.651)
  Bottom Layer w0.2: TYPE.5 TYPE.5 v1@-1.841,22.651
NetR5_2: R5.2 U2.2 | length 5.3
  Top Layer w0.2: R5.2 -17.001,12.523 -16.661,12.183 U2.2
NetR6_1: R6.1 U2.7 | length 14.6
  Top Layer w0.2: U2.7 -8.849,12.183 -8.641,11.976 v1(-8.641,9.821)
  Bottom Layer w0.2: R6.1 -15.281,11.011 -14.091,9.821 v1(-8.641,9.821)
NetR11_1: R11.1 U1.30 | length 6.6
  Bottom Layer w0.15: U1.30 -39.916,10.722 -39.031,9.837 -39.031,6.179 -38.944,6.091 -38.289,6.091 R11.1
NetU1_12: 
NetU4_47: U1.47 X1.1 | length 7.6
  Bottom Layer w0.15: X1.1 -48.621,15.411 -47.301,15.411 -46.268,16.445 U1.47
NetU4_48: U1.48 X1.3 | length 5.3
  Bottom Layer w0.15: X1.3 -47.611,16.161 -47.069,16.161 -46.385,16.845 U1.48
NTC: BAT.2 pad.28 R3.2 R4.1 U2.1 | length 20.9
  Top Layer w0.3: U2.1 -15.391,13.508 -15.391,14.411 -15.881,14.901 R4.1 R3.2@-14.921,16.081 ; v1(-8.051,14.391) -8.051,10.831 -7.391,10.171 BAT.2
  Bottom Layer w0.3: v1(-15.391,14.401) -15.386,14.396 -8.056,14.396 v1(-8.051,14.391)
NUM: R32.2 U1.7 | length 26.3
  Top Layer w0.15: v1(-24.11,9.61) -21.595,9.61 -21.355,9.85 v1(-21.26,9.85)
  Bottom Layer w0.15: U1.7 -39.916,18.826 -38.807,19.936 -34.357,19.936 -26.449,12.028 -25.474,12.028 -24.11,10.664 v1(-24.11,9.61) ; v1(-21.26,9.85) -20.292,9.85 R32.2
PWM: ARGB1.4 U1.32 | length 30.4
  Top Layer w0.15: v1(-55.36,6.02) -55.36,5.12 -54.33,4.09 -41.66,4.09 -41.491,3.921 -40.598,3.921 v1(-40.591,3.914)
  Bottom Layer w0.15: v1(-55.36,6.02) -55.31,6.02 -54.461,6.869 -54.461,10.431 -54.301,10.591 ARGB1.4 ; U1.32 -40.716,10.535 -39.779,9.598 -39.779,4.691 -40.556,3.914 v1(-40.591,3.914)
PWM_OFF: 
R0: pad.21 U1.37 | length 16.5
  Top Layer w0.15: pad.21 -40.91,-0.383 v1(-40.91,1.92)
  Bottom Layer w0.15: U1.37 -43.796,12.445 -44.921,11.319 -44.921,5.191 -42.84,3.11 -41.36,3.11 -40.91,2.66 v1(-40.91,1.92)
R1: pad.22 U1.38 | length 15.6
  Top Layer w0.15: pad.22@-42.78,1.94 -42.78,-0.346 pad.22
  Bottom Layer w0.15: U1.38 -43.889,12.845 -45.27,11.464 -45.27,5.047 -42.77,2.546 v1(-42.77,1.94)
R2: pad.23 U1.39 | length 15.6
  Top Layer w0.15: v1(-44.65,2.93) -44.615,2.895 pad.23
  Bottom Layer w0.15: v1(-44.65,2.93) -44.65,3.89 -45.619,4.859 -45.619,11.608 -43.983,13.245 U1.39
R3: pad. U1.40 | length 20.7
  Top Layer w0.15: pad.@-52.19,-0.256 pad.
  Top Layer w0.4: pad.@-52.19,-0.256 v1(-52.19,2.83)
  Bottom Layer w0.15: v1(-52.19,2.83) -51.81,3.21 -47.636,3.21 -45.968,4.878 -45.968,11.753 -44.076,13.645 U1.40
R4: pad.25 U1.41 | length 22.6
  Top Layer w0.15: v1@-54.031,2.899 v1(-53.99,2.94)
  Top Layer w0.4: pad.25 v1@-54.031,2.899
  Bottom Layer w0.15: v1(-53.99,2.94) -53.371,3.559 -47.945,3.559 -46.317,5.186 -46.317,11.897 -44.17,14.045 U1.41
R5: pad.26 U1.42 | length 24.8
  Top Layer w0.15: v1@-55.881,3.119 v1(-55.84,3.16)
  Top Layer w0.4: pad.26 v1@-55.881,3.119
  Bottom Layer w0.15: v1(-55.84,3.16) -55.092,3.908 -48.089,3.908 -46.666,5.331 -46.666,12.042 -44.263,14.445 U1.42
R6: ?.1@-57.74,-0.31 U1.43 | length 26.9
  Top Layer w0.15: ?.1@-57.74,-0.31 ?.1@-57.71,-0.281
  Top Layer w0.4: ?.1@-57.71,-0.281 v1(-57.71,3.27)
  Bottom Layer w0.15: v1(-57.71,3.27) -56.723,4.257 -48.234,4.257 -47.015,5.475 -47.015,12.186 -44.357,14.845 U1.43
R7: pad.30@-59.56,-0.34 U1.44 | length 29
  Top Layer w0.5: v1(-59.57,3.27) -59.56,3.26 pad.30@-59.56,-0.34
  Bottom Layer w0.15: v1(-59.57,3.27) -58.234,4.606 -48.378,4.606 -47.364,5.62 -47.364,12.331 -44.451,15.245 U1.44
SGND: C11.1 R23.1 TYPE.0 | length 21.1
  Top Layer w0.5: TYPE.0@0.729,25.801 0.729,18.716 0.759,18.686 C11.1 ; C11.1@0.779,18.666 R23.1
  Bottom Layer w0.5: TYPE.0@-7.911,25.791 TYPE.0@-7.901,25.801
  Bottom Layer w1: TYPE.0@-7.911,21.641 TYPE.0@-7.911,25.791 ; TYPE.0@-7.901,25.801 TYPE.0@0.729,25.801
SS1: 
USB_5V: C3.2 C12.2 R0.2 TYPE.3 TYPE.4 TYPE.13 TYPE.14 | length 13.1
  Top Layer w0.5: R0.2@-12.941,19.341 v1(-6.001,19.341) v1(-2.17,19.341)
  Bottom Layer w0.5: v1(-6.001,19.341) -6.001,20.161 ; v1(-2.17,19.341) -1.471,19.341 -1.151,19.661 -1.151,19.971
V33: 54V.1 C8.1 C9.1 U1.28 U1.33 | length 8.7
  Top Layer w0.5: v1(-41.23,9) -40.322,9 54V.1
  Bottom Layer w0.15: v1@-41.204,9.026 -41.194,9.036 -40.831,9.036 ; C9.1 -40.64,9.135 -40.64,9.91 -41.116,10.386 U1.33 -41.116,12.326 -41.001,12.441 -39.291,12.441 -39.116,12.266 U1.28
  Bottom Layer w0.4: C8.1@-41.76,9.008 -41.238,9.008 v1(-41.23,9) -41.214,9.016 -40.761,9.016
VBAT: ARGB1.3 ARGB.3 C10.1 D1.2 D2.2 D3.2 T3.1@-50.478,8.24 U1.34 VBAT.1 | length 73.9
  Top Layer w0.3: v1(-41.4,9.79) -41.06,10.13 -36.18,10.13 VBAT.1 -35.755,9.775 -33.545,9.775 v1(-33.51,9.81)
  Top Layer w0.4: ARGB.3 -59.551,15.381 -59.551,10.721 -58.991,10.161 -52.399,10.161 v1(-51.601,9.361) -50.478,8.24 -47.501,5.263 -34.263,5.263 v1(-34.26,5.26) ; v1(-33.51,9.81) -25.989,9.81 -25.09,8.911 -20.929,8.911 -20.33,9.51 -20.33,14.33 -20.54,14.54 D2.2@-20.81,14.54
  Top Layer w0.5: D1.2 -20.62,14.81 D2.2@-20.58,14.77
  Bottom Layer w0.15: U1.34 -41.509,11.637 -41.509,9.994 -41.4,9.885 v1(-41.4,9.79)
  Bottom Layer w0.4: ARGB1.3 -51.611,9.351 v1(-51.601,9.361) ; v1(-34.26,5.26) -33.51,6.01 v1(-33.51,9.81)
  Bottom Layer w0.5: C10.1 -41.409,9.781 v1(-41.4,9.79)
VCC: 
VDD: 
VPP: R11.2 U1.29 VPP.1 | length 5.4
  Top Layer w0.15: v1(-38.373,9.092) VPP.1
  Bottom Layer w0.15: U1.29 -39.516,10.816 -38.351,9.651 v1@-38.351,9.131 ; v1@-38.411,9.131 v1(-38.373,9.092) ; R11.2@-38.351,6.971 v1@-38.351,9.092
WHA: 
WHB: 
pads on no net: SW1. SW1.3 TYPE.6 TYPE.12 U1.2 U2.6

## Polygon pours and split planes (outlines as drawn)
GND on Top Layer "gnd1" (solid, remove dead copper, pour order 1): -65.039,17.523 -64.773,17.257 -52.129,17.257 -50.109,19.277 -49.969,19.277 -43.638,19.277 -42.998,19.897 -42.939,19.897 -41.769,19.897 -41.619,20.047 -41.619,22.097 -38.643,25.073 -14.971,25.073 -14.971,26.873 5.529,26.873 5.529,-2.927 cw(c3.529,-2.927) 3.529,-4.927 -65.521,-4.927 -65.521,17.523
GND on Bottom Layer "gnd1" (solid, remove dead copper, pour order 0): -65.161,17.427 -64.896,17.161 -52.251,17.161 -50.231,19.181 -50.091,19.181 -43.761,19.181 -43.121,19.801 -43.061,19.801 -41.891,19.801 -41.741,19.951 -41.741,22.001 -38.766,24.977 -15.094,24.977 -15.094,26.777 5.406,26.777 5.406,-3.023 cw(c3.406,-3.024) 3.406,-5.023 -65.644,-5.023 -65.644,17.427

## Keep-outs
Keep-Out Layer:
  circle w0.1: c-9.394,-0.223 r2.35
  circle w0.1: c-9.394,-0.223 r2.35
  circle w0.1: c-48.394,-0.223 r2.35
  circle w0.1: c-48.394,-0.223 r2.35
  lines w0.1: -65.644,-5.023 3.406,-5.023 ccw(c3.406,-3.023) 5.406,-3.023 5.406,26.777 -15.094,26.777 -15.094,24.977 -55.934,24.977 -55.934,21.427 cw(c-59.934,21.427) -59.934,17.427 -65.644,17.427 -65.644,-5.023

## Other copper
Top Layer:
  pour cut-out: -65.8,3.695 -65.74,3.755 5.6,3.755 5.96,3.395 5.96,1.085 -65.76,1.085 -65.98,1.305 -65.98,3.595 -65.94,3.595 -65.79,3.745
Bottom Layer:
  rectangle net NetANT1_1: -43.381,24.081 -42.181,24.481
  pour cut-out: -59.641,3.619 -59.62,3.64 -3.113,3.64 1.89,3.64 2.57,2.96 2.57,-0.478 2.025,-1.023 -59.91,-1.023 -60.382,-0.55 -60.382,3.278 -60.042,3.619

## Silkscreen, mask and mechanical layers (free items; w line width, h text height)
Top Overlay:
  lines w0.1: -56.431,15.501 -57.001,16.071 -52.071,16.071
  text "BYKC-RX-RX12-6252-ARGB-V0" at -51.239,18.332 h1.8
  text "- IO +" at -57.101,17.451 h1 r180
  text "20261016  ZJH" at -44.283,16.678 h1.5
  text "FR4/T1.2mm" at -43.741,15.048 h1.5
  text "+T-" at -6.871,8.211 h1.5 r270
  text "C18" at -17.31,4.66 h0.8 r270
  text "C15" at -19.56,4.5 h0.8
  text "C16" at -19.11,4.27 h0.8 r270
  text "R7" at -59.978,3.11 h0.8 r270
  text "R6" at -58.377,3.11 h0.8 r270
  text "R5" at -56.703,3.11 h0.8 r270
  text "R4" at -54.67,3.11 h0.8 r270
  text "R3" at -52.64,3.11 h0.8 r270
  text "R2" at -44.998,3.11 h0.8 r270
  text "R1" at -43.152,3.11 h0.8 r270
  text "R0" at -41.306,3.11 h0.8 r270
  text "C5" at -39.461,3.11 h0.8 r270
  text "C6" at -37.615,3.11 h0.8 r270
  text "C7" at -35.769,3.11 h0.8 r270
  text "C8" at -33.923,3.11 h0.8 r270
  text "C9" at -32.078,3.11 h0.8 r270
  text "C10" at -30.232,3.11 h0.8 r270
  text "C11" at -28.386,3.11 h0.8 r270
  text "C12" at -26.54,3.11 h0.8 r270
  text "C13" at -24.695,3.11 h0.8 r270
  text "C14" at -22.849,3.11 h0.8 r270
  text "C4" at -15.466,3.11 h0.8 r270
  text "C3" at -13.62,3.11 h0.8 r270
  text "C2" at -6.07,3.11 h0.8 r270
  text "C1" at -4.25,3.11 h0.8 r270
  text "C0" at -2.39,3.11 h0.8 r270
  text "C17" at -0.52,3.11 h0.8 r270
  text "C19" at 1.35,3.11 h0.8 r270
Bottom Overlay:
  circle w0.1: c-25.094,23.477 r0.4
  circle w0.1: c-30.094,23.477 r0.4
  rectangle: -41.651,12.131 -38.591,12.721
  lines w0.1: -32.944,22.127 -22.244,22.127 ; -32.944,24.827 -22.244,24.827 ; -28.244,24.827 -28.244,24.977 -28.244,26.027 ; -26.944,24.827 -26.944,24.977 -26.944,26.027 ; -8.064,24.977 -8.064,21.127 0.876,21.127 0.876,24.977 ; -8.064,28.119 -8.064,28.477 0.876,28.477 0.876,28.119 ; -7.914,28.477 -7.764,28.177 -7.764,26.427 ; -7.764,21.127 -7.764,24.977 ; -7.764,21.427 0.576,21.427 ; 0.576,21.127 0.576,24.977 ; 0.576,26.427 0.576,28.177 0.726,28.477 ; -28.244,26.027 cw(c-27.944,26.027) -27.944,26.327 -27.244,26.327 cw(c-27.244,26.027) -26.944,26.027 ; -28.244,26.027 -26.944,26.027 ; -32.444,22.327 ccw(c-32.244,22.327) -32.244,22.127 -32.244,24.827 ccw(c-32.244,24.627) -32.444,24.627 -22.744,24.627 ccw(c-22.944,24.627) -22.944,24.827 -22.944,22.127 ccw(c-22.944,22.327) -22.744,22.327 -32.444,22.327
  text "BT" at -19.211,22.701 h2
  text "2G4" at -33.75,22.603 h2
Top Solder:
  rectangle: -7.05,-3.76 3.34,2.78
  rectangle: -45.98,-3.71 -11.77,2.78
  rectangle: -60.47,-3.7 -50.76,2.8
Bottom Solder:
  rectangle: -55.911,20.611 -43.06,24.961
Mechanical 1:
  drawing of 212 lines, arcs and shapes, not listed
  text "PCB_无线_3M}" at -71.551,147.768 h12.43
  text "厚度1.2" at -34.981,32.736 h5
  text "TypeC反贴" at -7.721,29.597 h2
  text "指示灯正反贴都可" at -58.251,28.107 h1.5
  text "三段反贴" at -30.57,27.147 h1.5
  text "（灯光要在反面 M-LED灯）" at -60.154,26.327 h1.5
  text "2.4G" at -35.383,25.773 h2
  text "BT" at -23.631,25.771 h2
  text "Caps灯}" at -37.291,11.922 h1.5
  text "Num灯}" at -18.671,11.872 h1.5
  text "插线方向}" at 6.409,11.759 h1
  text "电池插座1.25端子3P" at 6.299,9.552 h1
  text "(正面贴片）" at 6.379,7.59 h1
  text "金手指在正面}" at -35.93,-13.588 h3.31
